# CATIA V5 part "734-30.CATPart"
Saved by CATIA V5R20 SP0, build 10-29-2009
Part number: 734-30
Bounding box of the stored display mesh (mm): x -28 to 28, y -28 to 28, z -37 to 56
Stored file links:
  C:\Users\Utente\Desktop\IO LAVORO\3D X SITO CF\X SITO\734\734-30.CATPart
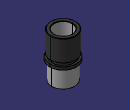
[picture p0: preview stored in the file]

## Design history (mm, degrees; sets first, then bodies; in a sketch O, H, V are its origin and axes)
Set1
  DatumSurface1 to DatumSurface25 "734-30"
Body1 (main body)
